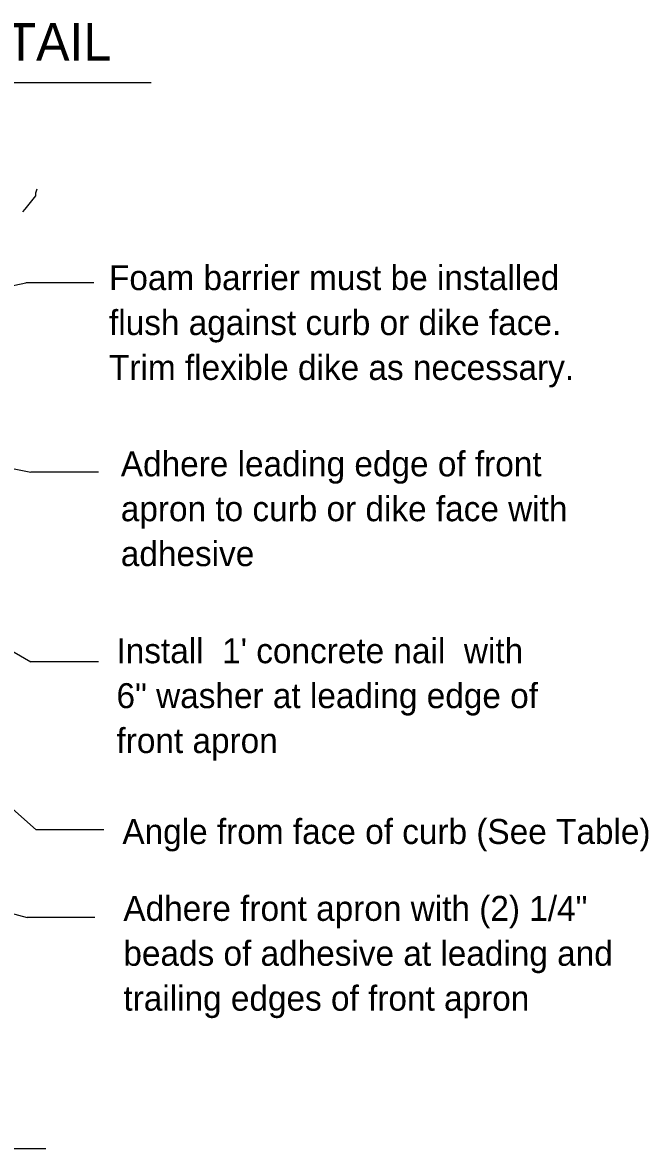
# Model space of a CAD drawing. Extents: x 6708945 to 6710368, y 1871409 to 1872338.
# Drawn here: x 6709843.2 to 6709993.8, y 1871758.9 to 1872029.7 of the extents above; entities that cross this region are included whole.
import ezdxf

# ---------------------------------------------------------------- set-up
doc = ezdxf.new("R2010")
doc.units = 0
doc.layers.add('57 Undefined', color=7, linetype='Continuous')
doc.layers.add('60 Nongeo Data', color=7, linetype='Continuous')

msp = doc.modelspace()

# ---------------------------------------------------------------- linework, layer by layer
at = {"layer": '57 Undefined'}
for p, q in [((6709723.08, 1872015.26), (6709874.13, 1872015.26)), ((6709735.76, 1871944.57), (6709844.01, 1871967.11)), ((6709860.3, 1871967.11), (6709844.01, 1871967.11)), ((6709763.76, 1871937.4), (6709845.14, 1871921.6)), ((6709757.25, 1871926.98), (6709845.14, 1871876)), ((6709861.42, 1871921.6), (6709845.14, 1871921.6)), ((6709777.83, 1871896.35), (6709846.44, 1871835.61)), ((6709861.42, 1871876), (6709845.14, 1871876)), ((6709710.36, 1871850.75), (6709844.26, 1871814.52)), ((6709862.73, 1871835.61), (6709846.44, 1871835.61)), ((6709860.55, 1871814.52), (6709844.26, 1871814.52)), ((6709751.68, 1871758.94), (6709848.82, 1871758.94))]:
    msp.add_line(p, q, dxfattribs=at)
at = {"layer": '60 Nongeo Data'}
msp.add_lwpolyline([(6709846.65, 1871989.63), (6709846.33, 1871988.67), (6709846.33, 1871988.03), (6709845.05, 1871986.44), (6709843.77, 1871984.84), (6709843.13, 1871984.2)], dxfattribs=at)

# ---------------------------------------------------------------- texts
at = {"layer": '57 Undefined'}
for s, height, p in [('FOAM BARRIER DETAIL', 9, (6709727.43, 1872020.58)), ('Foam barrier must be installed', 6, (6709863.99, 1871965.36)), ('flush against curb or dike face.', 6, (6709863.99, 1871954.56)), ('Trim flexible dike as necessary.', 6, (6709863.99, 1871943.76)), ('Adhere leading edge of front', 6, (6709866.83, 1871920.59)), ('apron to curb or dike face with', 6, (6709866.83, 1871909.79)), ('adhesive', 6, (6709866.83, 1871898.99)), ("Install  1' concrete nail  with ", 6, (6709865.79, 1871875.64)), ('6" washer at leading edge of', 6, (6709865.79, 1871864.84)), ('front apron', 6, (6709865.79, 1871854.04)), ('Angle from face of curb (See Table)', 6, (6709867.21, 1871832.17)), ('Adhere front apron with (2) 1/4" ', 6, (6709867.45, 1871813.68)), ('beads of adhesive at leading and ', 6, (6709867.45, 1871802.88)), ('trailing edges of front apron', 6, (6709867.45, 1871792.08))]:
    msp.add_text(s, height=height, dxfattribs=at).set_placement(p)

doc.saveas('drawing.dxf')
